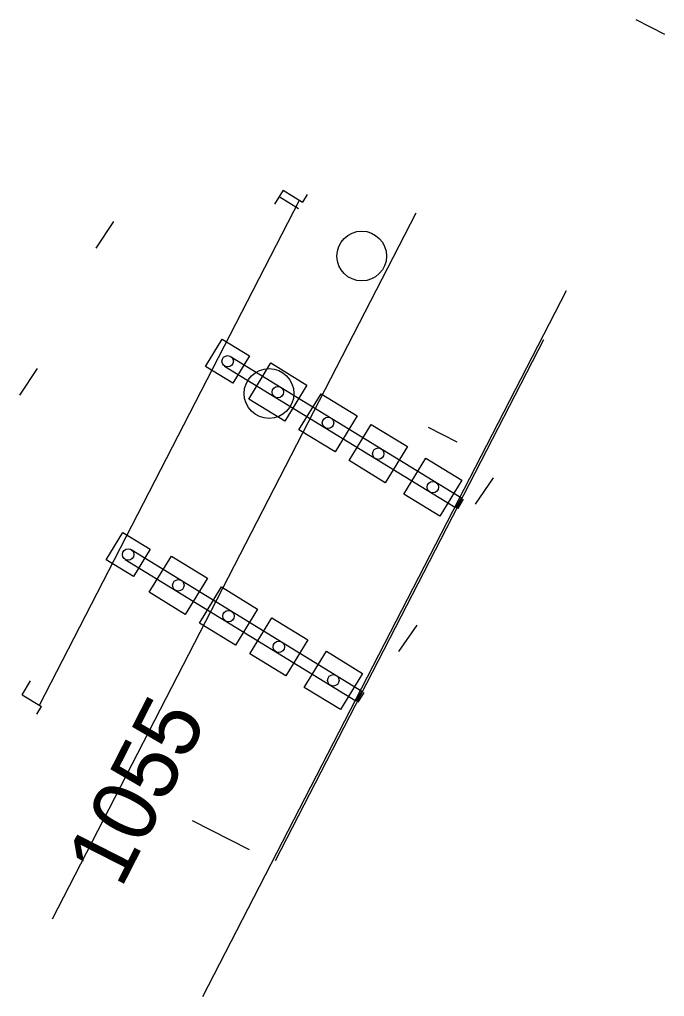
# Model space of a CAD drawing. Extents: x -845213 to 599959, y -257022 to 229056.
# Drawn here: x -845213 to -845072.1, y -257022.1 to -256808.6 of the extents above; entities that cross this region are included whole.
import ezdxf

# ---------------------------------------------------------------- set-up
doc = ezdxf.new("R2010")
doc.units = 0
for name, color, linetype in [('E_NO PLOT', 7, 'Continuous'), ('N_PTS_NODE', 7, 'Continuous'), ('P_ALI_100_PIData', 7, 'Continuous'), ('P_ALI_100_Sta', 7, 'Continuous'), ('P_ALI_100_Tic', 7, 'Continuous')]:
    doc.layers.add(name, color=color, linetype=linetype)

msp = doc.modelspace()

# ---------------------------------------------------------------- linework, layer by layer
at = {"layer": 'E_NO PLOT'}
for p, q in [((-845205.82, -257005.14), (-845126.36, -256850.86)), ((-845172.93, -257022.08), (-845093.46, -256867.8))]:
    msp.add_line(p, q, dxfattribs=at)
at = {"layer": 'N_PTS_NODE'}
for p, q in [((-845155.41, -256845.87), (-845157.28, -256848.92)), ((-845155.41, -256845.87), (-845151.14, -256848.48)), ((-845208.68, -256958.45), (-845151.82, -256848.07)), ((-845156.28, -256847.29), (-845152.02, -256849.9)), ((-845150.14, -256846.85), (-845151.14, -256848.48)), ((-845157.05, -256992.35), (-845098.44, -256878.54)), ((-845166.89, -256882.2), (-845116.45, -256913.13)), ((-845168.2, -256884.33), (-845117.75, -256915.26)), ((-845116.45, -256913.13), (-845117.75, -256915.26)), ((-845116.02, -256913.39), (-845117.33, -256915.52)), ((-845188.64, -256924.43), (-845138.2, -256955.35)), ((-845189.95, -256926.56), (-845139.5, -256957.49)), ((-845212.48, -256956.13), (-845210.6, -256953.07)), ((-845212.48, -256956.13), (-845208.21, -256958.74)), ((-845138.2, -256955.35), (-845139.5, -256957.49)), ((-845137.77, -256955.62), (-845139.08, -256957.75)), ((-845209.22, -256960.37), (-845208.21, -256958.74))]:
    msp.add_line(p, q, dxfattribs=at)
for points in [[(-845166.39, -256888.08), (-845172.36, -256884.42), (-845168.7, -256878.46), (-845162.73, -256882.11)], [(-845158.09, -256883.64), (-845150.21, -256888.47), (-845155.04, -256896.36), (-845162.93, -256891.52)], [(-845147.12, -256890.37), (-845139.23, -256895.2), (-845144.06, -256903.09), (-845151.95, -256898.25)], [(-845136.14, -256897.1), (-845128.25, -256901.93), (-845133.09, -256909.82), (-845140.97, -256904.98)], [(-845124.2, -256904.41), (-845116.32, -256909.25), (-845121.15, -256917.13), (-845129.04, -256912.3)], [(-845188.14, -256930.31), (-845194.11, -256926.65), (-845190.45, -256920.68), (-845184.48, -256924.34)], [(-845179.84, -256925.87), (-845171.96, -256930.7), (-845176.79, -256938.59), (-845184.68, -256933.75)], [(-845168.87, -256932.59), (-845160.98, -256937.43), (-845165.81, -256945.32), (-845173.7, -256940.48)], [(-845157.89, -256939.32), (-845150, -256944.16), (-845154.84, -256952.04), (-845162.72, -256947.21)], [(-845145.95, -256946.64), (-845138.07, -256951.47), (-845142.9, -256959.36), (-845150.79, -256954.53)]]:
    msp.add_lwpolyline(points, close=True, dxfattribs=at)
for centre in [(-845167.54, -256883.27), (-845156.57, -256890), (-845145.59, -256896.73), (-845134.61, -256903.46), (-845122.68, -256910.77), (-845189.29, -256925.5), (-845178.32, -256932.23), (-845167.34, -256938.95), (-845156.36, -256945.68), (-845144.43, -256953)]:
    msp.add_circle(centre, 1.25, dxfattribs=at)
at = {"layer": 'P_ALI_100_PIData'}
for centre in [(-845138.23, -256860.27), (-845158.49, -256890.32)]:
    msp.add_circle(centre, 5.44, dxfattribs=at)
at = {"layer": 'P_ALI_100_Tic'}
for points in [[(-845078.29, -256808.59), (-845072.06, -256811.76)], [(-845192.51, -256852.73), (-845196.36, -256858.57)], [(-845209.17, -256884.86), (-845213.02, -256890.7)], [(-845123.68, -256897.7), (-845117.44, -256900.87)], [(-845109.48, -256908.73), (-845113.46, -256914.49)], [(-845126.19, -256940.94), (-845130.17, -256946.7)], [(-845175.3, -256983.63), (-845162.82, -256989.98)]]:
    msp.add_lwpolyline(points, dxfattribs=at)

# ---------------------------------------------------------------- texts
at = {"layer": 'P_ALI_100_Sta'}
msp.add_text('1055', height=14, rotation=63.0098, dxfattribs=at).set_placement((-845190.84, -256998.72))

doc.saveas('drawing.dxf')
